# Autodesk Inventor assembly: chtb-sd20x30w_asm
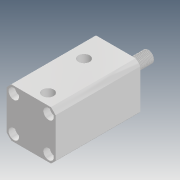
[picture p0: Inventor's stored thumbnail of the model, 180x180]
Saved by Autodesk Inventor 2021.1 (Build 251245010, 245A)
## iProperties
Company: Microsoft
Created: 2018-05
Part Number: chtb-sd20x30w_asm
Description: STEP AP214
Document SubType Name: Assembly
Designer: user
Title: chtb-sd20x30w_asm.STEP
Author: Windows
Revision Number: ÈÎºÎ
Sending System: SolidWorks 2015
Preprocessor: SwSTEP 2.0
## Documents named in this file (4)
- D:\Vault_2016\Projekty\Clamptek\Hydraulic\CHTB\CHTB-20\Inventor\CHTB-SD20x30W\chtb-sd20x30w_asm.iam
- D:\Vault_2016\Projekty\Clamptek\Hydraulic\CHTB\CHTB-20\Inventor\CHTB-SD20x30W\CHTB-SD20X30NBT.ipt
- D:\Vault_2016\Projekty\Clamptek\Hydraulic\CHTB\CHTB-20\Inventor\CHTB-SD20x30W\CHTB-SD20X30WHSG.ipt
- D:\Vault_2016\Projekty\Clamptek\Hydraulic\CHTB\CHTB-20\Inventor\CHTB-SD20x30W\QG.ipt
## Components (3 placed, 3 different names)
1. CHTB-SD20X30NBT_1
2. CHTB-SD20X30WHSG_2
3. QG_3
